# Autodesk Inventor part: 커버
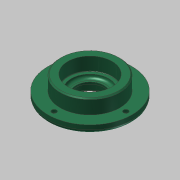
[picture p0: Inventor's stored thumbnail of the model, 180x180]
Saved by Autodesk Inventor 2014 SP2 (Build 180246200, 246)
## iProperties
Company: 한국ATC센터
Created: 2016-04
Part Number: 커버
Document SubType Name: Modeling
Designer: mdu
Density: 7.86 g/cm^3
Mass: 351.567 g
Surface Area: 161.165 cm^2
Volume: 44.7286 cm^3
Material: 강철, 연강
Appearance: 강철
Author: mdu
Revision Number: 1
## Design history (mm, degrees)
sketch "스케치1"
  geometry: C1 r 38 at (0, 0); 1 further point
  constraints: 1 centre point, 1 coincident
  dimensions: "d0" = 76 diameter of C1
extrude "돌출1" new body sketch "스케치1" distance "d1" = 7; taper "d2" = 0 deg
sketch "스케치2"
  geometry: C1 r 27 at (0, 0); 1 further point
  constraints: 1 centre point, 1 coincident
  dimensions: "d3" = 54 diameter of C1
extrude "돌출2" join sketch "스케치2" distance "d4" = 13; taper "d5" = 0 deg
sketch "스케치3"
  geometry: C1 r 20 at (0, 0); 1 further point
  constraints: 1 centre point, 1 coincident
  dimensions: "d6" = 40 diameter of C1
extrude "돌출3" join sketch "스케치3" distance "d7" = 5; taper "d8" = 0 deg
hole "구멍1" diameter "d11" = 25; stored, may be unused: countersink angle "d15" = 90 deg, drill point angle "d17" = 118 deg; dims "d9" = 10, "d10" = 10, "d12" = 6, "d13" = 32, "d14" = 8.3, "d16" = 8
hole "구멍2" diameter "d20" = 34; stored, may be unused: countersink angle "d24" = 90 deg, drill point angle "d26" = 0 deg; dims "d18" = 10, "d19" = 10, "d21" = 6, "d22" = 40, "d23" = 12, "d25" = 3
fillet "모깎기2" dims "d34" = 3
fillet "모깎기1" dims "d27" = 0.3
chamfer "모따기1" distance "d28" = 1; stored, may be unused: second distance "d29" = 2, angle "d30" = 45 deg
chamfer "모따기2" distance "d31" = 1.2; stored, may be unused: second distance "d32" = 2, angle "d33" = 30 deg
sketch "스케치4" dims "d35" = 65
  geometry: 3 further points
  constraints: 2 horizontal alignment, 1 coincident, 2 other
hole "구멍3" sketch "스케치4" at (32.5, 0) diameter "d36" = 4.5; stored, may be unused: countersink angle "d40" = 90 deg, drill point angle "d42" = 118 deg; dims "d37" = 6, "d38" = 8, "d39" = 4.4, "d41" = 13
node "솔리드1"
pattern_circular "원형 패턴1" dims angle "d44" = 360 deg
